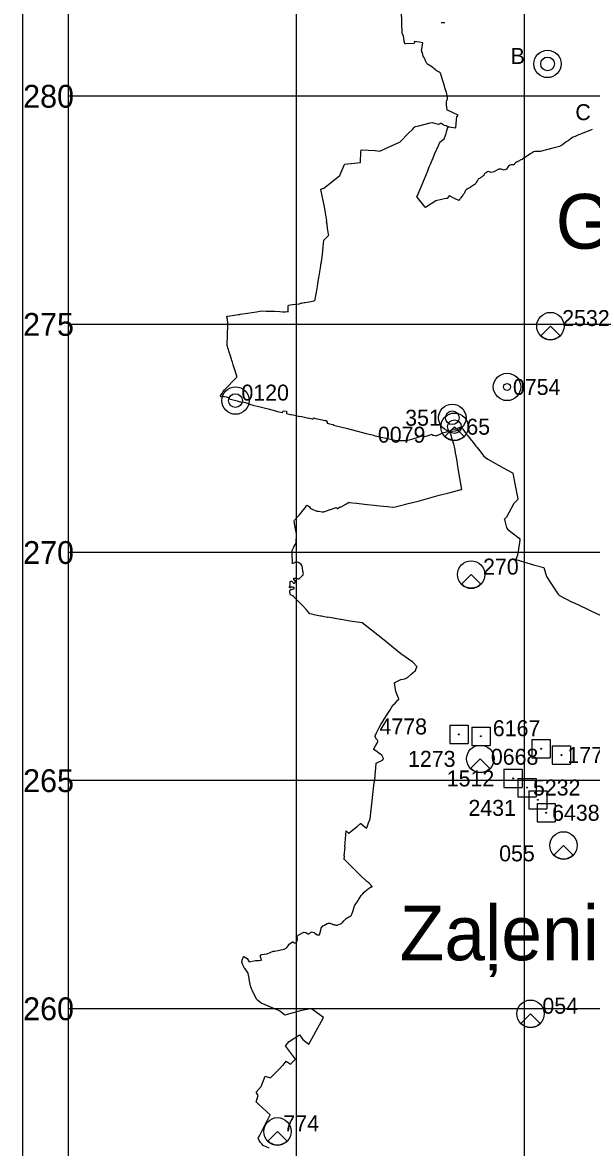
# Model space of a CAD drawing. Extents: x 459000 to 506121, y 222400 to 317452.
# Drawn here: x 459000 to 471473, y 256960 to 281617 of the extents above; entities that cross this region are included whole.
import ezdxf

# ---------------------------------------------------------------- set-up
doc = ezdxf.new("R2010")
doc.units = 0
for name, color, linetype in [('grunts_reperi', 7, 'Continuous'), ('novada_robeza', 7, 'Continuous'), ('pagastu_nosaukumi', 7, 'Continuous'), ('pagastu_robezas', 7, 'Continuous'), ('Ramis', 7, 'Continuous'), ('savietotie_ar_poligonometrijas_punktiem', 7, 'Continuous'), ('sienas_markas', 7, 'Continuous'), ('sienas_reperi', 7, 'Continuous')]:
    doc.layers.add(name, color=color, linetype=linetype)

msp = doc.modelspace()

# ---------------------------------------------------------------- linework, layer by layer
at = {"layer": 'grunts_reperi'}
for radius in [300, 75]:
    msp.add_circle((469621, 273629), radius, dxfattribs=at)
at = {"layer": 'novada_robeza'}
for points in [[(468327, 279317), (468330, 279314), (468334, 279322), (468335, 279328), (468336, 279334), (468343, 279334), (468346, 279333), (468496, 279311), (468516, 279490), (468522, 279550), (468549, 279589), (468316, 279694), (468309, 279697), (468306, 279721), (468303, 279739), (468300, 279765), (468297, 279789), (468296, 279798), (468292, 279822), (468291, 279847), (468293, 279865), (468295, 279879), (468304, 279909), (468315, 279947), (468318, 279961), (468319, 279968), (468318, 279983), (468316, 279998), (468310, 280019), (468291, 280079), (468266, 280164), (468233, 280274), (468214, 280341), (468186, 280433), (468183, 280443), (468170, 280486), (468166, 280497), (468161, 280506), (468156, 280512), (468148, 280520), (468144, 280522), (468139, 280526), (468111, 280540), (468087, 280552), (468071, 280562), (468057, 280573), (468043, 280584), (467948, 280656), (467881, 280704), (467880, 280705), (467864, 280721), (467849, 280744), (467834, 280774), (467810, 280832), (467802, 280845), (467799, 280849), (467796, 280854), (467794, 280858), (467782, 280878), (467766, 280951), (467754, 280975), (467749, 281009), (467748, 281012), (467752, 281034), (467775, 281173), (467698, 281184), (467596, 281202), (467590, 281200), (467589, 281193), (467591, 281174), (467588, 281155), (467395, 281146), (467387, 281146), (467383, 281148), (467381, 281149), (467368, 281199), (467368, 281214), (467349, 281325), (467326, 281375), (467314, 281614), (467307, 281871)], [(468178, 281619), (468196, 281616), (468211, 281616), (468217, 281615), (468222, 281614), (468237, 281615), (468242, 281614), (468243, 281614), (468251, 281616), (468259, 281617)], [(463333, 273425), (463338, 273433), (463367, 273477), (463399, 273528), (463425, 273566), (463687, 273827), (463697, 273847), (463698, 273866), (463641, 274046), (463619, 274114), (463617, 274117), (463600, 274170), (463588, 274208), (463579, 274235), (463550, 274330), (463532, 274393), (463486, 274538), (463483, 274549), (463487, 274624), (463493, 274695), (463497, 274805), (463497, 274805), (463502, 274947), (463501, 274947), (463501, 274952), (463500, 274981), (463500, 274994), (463501, 275007), (463501, 275027), (463501, 275038), (463500, 275055), (463498, 275067), (463496, 275080), (463494, 275093), (463492, 275102), (463491, 275112), (463490, 275120), (463488, 275133), (463484, 275153), (463482, 275160), (463481, 275166), (463480, 275174), (463501, 275178), (463734, 275216), (463755, 275219), (463774, 275222), (463930, 275247), (464028, 275262), (464128, 275278), (464240, 275296), (464342, 275293), (464472, 275287), (464481, 275287), (464525, 275287), (464642, 275281), (464698, 275278), (464725, 275277), (464756, 275277), (464799, 275280), (464828, 275282), (464827, 275286), (464825, 275389), (464829, 275421), (464918, 275434), (464987, 275443), (465069, 275453), (465072, 275450), (465075, 275454), (465087, 275460), (465095, 275463), (465115, 275467), (465172, 275477), (465198, 275480), (465331, 275503), (465387, 275518), (465402, 275526), (465412, 275536), (465418, 275553), (465458, 275789), (465465, 275834), (465476, 275897), (465497, 276024), (465503, 276062), (465533, 276241), (465549, 276349), (465553, 276374), (465573, 276534), (465594, 276702), (465606, 276848), (465610, 276853), (465718, 276959), (465708, 276973), (465707, 276978), (465692, 277068), (465688, 277104), (465675, 277194), (465667, 277251), (465669, 277271), (465618, 277579), (465539, 277954), (465537, 277962), (465541, 277963), (465595, 277986), (465599, 277981), (465746, 278096), (465883, 278203), (465959, 278260), (465989, 278337), (466058, 278501), (466063, 278512), (466064, 278512), (466412, 278549), (466407, 278562), (466420, 278765), (466425, 278827), (466732, 278809), (466783, 278804), (466833, 278799), (466946, 278851), (467035, 278893), (467183, 278956), (467235, 278977), (467247, 278983), (467273, 278996), (467289, 279011), (467457, 279184), (467465, 279194), (467546, 279275), (467589, 279318), (467602, 279329), (467611, 279334), (467618, 279335), (467689, 279354), (467940, 279419), (467977, 279426), (468084, 279398), (468119, 279389), (468127, 279389), (468154, 279405), (468161, 279407), (468165, 279409), (468173, 279409), (468182, 279409), (468184, 279408), (468187, 279406), (468200, 279396), (468218, 279381), (468230, 279371), (468243, 279368), (468280, 279361), (468286, 279358), (468327, 279317)], [(463333, 273425), (463340, 273423), (463396, 273409), (463400, 273429), (463431, 273419), (463462, 273409), (463534, 273390), (463527, 273371), (463674, 273335), (463704, 273322), (463731, 273315), (463804, 273295), (463820, 273305), (463964, 273269), (463961, 273259), (463979, 273261), (463976, 273250), (464046, 273233), (464077, 273225), (464208, 273191), (464386, 273147), (464545, 273106), (464593, 273094), (464703, 273069), (464712, 273108), (464788, 273098), (464787, 273049), (464901, 273020), (464904, 273019), (464906, 273028), (465079, 272984), (465081, 272990), (465123, 272979), (465266, 272944), (465268, 272952), (465374, 272926), (465380, 272950), (465425, 272937), (465531, 272917), (465638, 272896), (465647, 272894), (465656, 272892), (465679, 272860), (465677, 272834), (465687, 272832), (465705, 272829), (465763, 272815), (465822, 272801), (465821, 272796), (465820, 272791), (465971, 272753), (466122, 272715), (466530, 272612), (466702, 272569), (466703, 272568), (466704, 272568), (466857, 272532), (467011, 272496), (467132, 272469), (467135, 272468), (467207, 272459), (467303, 272455), (467312, 272456), (467349, 272452), (467413, 272457), (467487, 272470), (467556, 272490), (467787, 272565), (467792, 272549), (467797, 272533), (467890, 272562), (467982, 272591), (467986, 272581), (467989, 272571), (468016, 272569), (468044, 272567), (468065, 272559), (468225, 272627), (468344, 272657), (468345, 272657), (468358, 272662), (468371, 272667)], [(463847, 261148), (463849, 261147), (463851, 261146), (463890, 261123), (463928, 261099), (463948, 261063), (463968, 261026), (464109, 261056), (464136, 261058), (464141, 261058), (464188, 261061), (464236, 261063), (464214, 261141), (464211, 261150), (464240, 261191), (464294, 261198), (464352, 261205), (464360, 261206), (464494, 261266), (464522, 261266), (464603, 261280), (464660, 261291), (464707, 261301), (464735, 261308), (464780, 261328), (464798, 261344), (464821, 261378), (464848, 261419), (464920, 261469), (464928, 261468), (464964, 261448), (464980, 261445), (464994, 261447), (465004, 261456), (465010, 261463), (465019, 261490), (465028, 261524), (465023, 261574), (465029, 261599), (465041, 261614), (465152, 261673), (465167, 261683), (465211, 261675), (465244, 261648), (465255, 261643), (465272, 261640), (465287, 261646), (465310, 261670), (465331, 261682), (465348, 261685), (465367, 261682), (465394, 261671), (465431, 261645), (465459, 261623), (465481, 261620), (465502, 261623), (465508, 261623), (465538, 261727), (465549, 261765), (465562, 261787), (465572, 261799), (465587, 261815), (465606, 261826), (465678, 261866), (465695, 261873), (465710, 261875), (465714, 261876), (465717, 261877), (465724, 261876), (465731, 261876), (465736, 261875), (465742, 261874), (465752, 261870), (465762, 261867), (465787, 261859), (465812, 261851), (465829, 261845), (465846, 261840), (465855, 261837), (465865, 261835), (465871, 261834), (465878, 261833), (465884, 261833), (465890, 261833), (465900, 261836), (465910, 261840), (465934, 261846), (465958, 261852), (465972, 261859), (465985, 261867), (465998, 261880), (466012, 261892), (466041, 261925), (466071, 261959), (466082, 261967), (466094, 261976), (466128, 261998), (466162, 262019), (466170, 262021), (466178, 262024), (466186, 262030), (466202, 262043), (466218, 262074), (466238, 262133), (466246, 262156), (466280, 262255), (466355, 262374), (466375, 262400), (466387, 262426), (466425, 262485), (466457, 262522), (466492, 262554), (466496, 262561), (466533, 262595), (466582, 262637), (466606, 262654), (466641, 262674), (466649, 262676), (466668, 262676), (466662, 262682), (466595, 262764), (466546, 262791), (466401, 262928), (466393, 262936), (466152, 263177), (466150, 263179), (466147, 263182), (466056, 263270), (466052, 263270), (466055, 263350), (466054, 263355), (466070, 263546), (466069, 263549), (466069, 263553), (466095, 263900), (466097, 263902), (466143, 263848), (466147, 263846), (466157, 263850), (466206, 263891), (466333, 263996), (466408, 264059), (466413, 264062), (466477, 264012), (466544, 263959), (466547, 263965), (466587, 264076), (466619, 264162), (466634, 264292), (466712, 264960), (466707, 264962), (466722, 265009), (466731, 265124), (466742, 265281), (466750, 265384), (466892, 265446), (466911, 265480), (466915, 265486), (466875, 265560), (466821, 265599), (466764, 265636), (466706, 265674), (466704, 265677), (466701, 265684), (466700, 265693), (466704, 265701), (466737, 265765), (466772, 265825), (466786, 265855), (466786, 265867), (466780, 265885), (466774, 265895), (466763, 265913), (466726, 265975), (466734, 265991), (466742, 266009), (466761, 266047), (466824, 266178), (466856, 266231), (466910, 266317), (466917, 266327), (467009, 266475), (467051, 266540), (467121, 266652), (467166, 266697), (467222, 266754), (467233, 266764), (467251, 266789), (467246, 266792), (467242, 266805), (467184, 266955), (467151, 267142), (467180, 267162), (467290, 267220), (467380, 267234), (467437, 267260), (467514, 267326), (467612, 267411), (467647, 267492), (467651, 267496), (467553, 267600), (467294, 267781), (467293, 267782), (466930, 268076), (466654, 268297), (466447, 268458), (466444, 268458), (466175, 268499), (465984, 268532), (465979, 268531), (465966, 268534), (465960, 268535), (465814, 268559), (465808, 268560), (465694, 268582), (465678, 268578), (465557, 268604), (465535, 268608), (465424, 268629), (465394, 268635), (465334, 268648), (465301, 268653), (465223, 268743), (465145, 268833), (465143, 268834), (465141, 268836), (465092, 268885), (465042, 268934), (465039, 268937), (465036, 268940), (465022, 268955), (465008, 268969), (464997, 268980), (464985, 268992), (464974, 269003), (464963, 269015), (464952, 269025), (464941, 269035), (464937, 269041), (464933, 269046), (464931, 269048), (464928, 269049), (464927, 269049), (464898, 269063), (464868, 269076), (464859, 269078), (464861, 269082), (464864, 269086), (464867, 269092), (464869, 269096), (464870, 269102), (464870, 269109), (464869, 269117), (464867, 269122), (464863, 269127), (464861, 269132), (464858, 269142), (464857, 269149), (464858, 269156), (464857, 269159), (464858, 269162), (464862, 269167), (464865, 269167), (464866, 269170), (464869, 269172), (464872, 269176), (464873, 269177), (464876, 269180), (464877, 269182), (464877, 269184), (464878, 269184), (464883, 269187), (464884, 269190), (464886, 269190), (464887, 269191), (464898, 269192), (464912, 269195), (464922, 269197), (464945, 269201), (464950, 269202), (464954, 269206), (464957, 269211), (464958, 269218), (464957, 269223), (464954, 269228), (464948, 269233), (464941, 269237), (464936, 269240), (464926, 269243), (464910, 269244), (464896, 269244), (464889, 269241), (464884, 269238), (464878, 269233), (464875, 269227), (464869, 269225), (464866, 269224), (464857, 269224), (464854, 269227), (464852, 269228), (464851, 269229), (464850, 269233), (464850, 269236), (464849, 269239), (464849, 269242), (464850, 269245), (464851, 269253), (464853, 269254), (464854, 269256), (464856, 269258), (464859, 269263), (464860, 269265), (464864, 269268), (464866, 269270), (464867, 269273), (464868, 269276), (464869, 269280), (464869, 269283), (464869, 269288), (464869, 269294), (464867, 269305), (464868, 269310), (464869, 269315), (464869, 269321), (464869, 269326), (464870, 269332), (464871, 269345), (464871, 269351), (464871, 269356), (464869, 269358), (464870, 269360), (464869, 269360), (464871, 269362), (464872, 269365), (464874, 269368), (464876, 269372), (464878, 269372), (464888, 269375), (464899, 269372), (464914, 269364), (464925, 269352), (464933, 269339), (464936, 269332), (464943, 269327), (464948, 269326), (464959, 269328), (464964, 269332), (464970, 269337), (464975, 269349), (464980, 269362), (464981, 269367), (464982, 269372), (464982, 269375), (464981, 269378), (464979, 269380), (464977, 269382), (464969, 269387), (464960, 269392), (464954, 269397), (464951, 269402), (464948, 269407), (464947, 269413), (464946, 269420), (464947, 269425), (464947, 269430), (464949, 269433), (464951, 269436), (464955, 269437), (464960, 269438), (464968, 269438), (464975, 269439), (464985, 269439), (464995, 269440), (464998, 269439), (465002, 269439), (465014, 269434), (465026, 269428), (465033, 269426), (465040, 269423), (465046, 269423), (465052, 269422), (465055, 269423), (465059, 269424), (465062, 269426), (465065, 269428), (465071, 269433), (465077, 269437), (465086, 269447), (465096, 269457), (465101, 269462), (465106, 269466), (465114, 269476), (465122, 269486), (465146, 269506), (465159, 269542), (465145, 269587), (465141, 269671), (465133, 269704), (465112, 269736), (465080, 269762), (465051, 269782), (465024, 269788), (464986, 269787), (464935, 269757), (464922, 269756), (464916, 269764), (464912, 269767), (464916, 269795), (464917, 269808), (464917, 269818), (464917, 269834), (464917, 269846), (464916, 269864), (464915, 269877), (464914, 269885), (464914, 269892), (464914, 269896), (464908, 269993), (464908, 270030), (464908, 270046), (464937, 270101), (464957, 270136), (464997, 270204), (464999, 270218), (465001, 270275), (464999, 270289), (465005, 270328), (465003, 270408), (464975, 270556), (464952, 270679), (464951, 270690), (464952, 270694), (464961, 270707), (465069, 270828), (465154, 270927), (465197, 270979), (465231, 271035), (465260, 271022), (465288, 271000), (465310, 270966), (465452, 270910), (465474, 270907), (465488, 270905), (465566, 270892), (465604, 270894), (465628, 270899), (465689, 270920), (465743, 270940), (465753, 270944), (465879, 270988), (465885, 270982), (465900, 270962), (465906, 270966), (465964, 271001), (465969, 270994), (466090, 271058), (466157, 271101), (466157, 271099), (466319, 271081), (466555, 271055), (466710, 271038), (466827, 271025), (466917, 271015), (467001, 271006), (467112, 270993), (467117, 270993), (467168, 271005), (467405, 271063), (467451, 271073), (467671, 271128), (468135, 271257), (468136, 271258), (468372, 271317), (468615, 271380), (468627, 271382), (468585, 271632), (468544, 271882), (468525, 271999), (468506, 272116), (468494, 272185), (468483, 272254), (468470, 272313), (468457, 272372), (468435, 272440), (468414, 272509), (468413, 272513), (468388, 272593), (468385, 272601), (468378, 272634), (468371, 272667)], [(464119, 257963), (464165, 258102), (464123, 258170), (464234, 258296), (464319, 258521), (464436, 258489), (464571, 258619), (464625, 258678), (464640, 258694), (464698, 258758), (464717, 258763), (464782, 258852), (464876, 258784), (464988, 258894), (464764, 259190), (464848, 259282), (465069, 259427), (465146, 259325), (465278, 259222), (465352, 259359), (465432, 259500), (465553, 259730), (465595, 259808), (465335, 260001), (465317, 260000), (465115, 259963), (464751, 259859), (464637, 259952), (464230, 260122), (464155, 260192), (464130, 260213), (464032, 260409), (464021, 260437), (464012, 260463), (464001, 260505), (463972, 260650), (463967, 260670), (463960, 260711), (463946, 260772), (463936, 260795), (463933, 260801), (463929, 260806), (463929, 260806), (463929, 260805), (463900, 260845), (463871, 260884), (463861, 260901), (463851, 260917), (463844, 260931), (463837, 260945), (463830, 260961), (463824, 260978), (463817, 261001), (463811, 261025), (463811, 261033), (463812, 261042), (463813, 261057), (463815, 261071), (463819, 261080), (463822, 261089), (463835, 261118), (463847, 261148)], [(464407, 256948), (464341, 256976), (464275, 257004), (464247, 257037), (464219, 257070), (464191, 257115), (464163, 257161), (464174, 257179), (464194, 257218), (464297, 257418), (464360, 257544), (464428, 257675), (464338, 257757), (464184, 257904), (464125, 257958), (464119, 257963)]]:
    msp.add_lwpolyline(points, dxfattribs=at)
at = {"layer": 'pagastu_robezas'}
for points in [[(471484, 279275), (471397, 279235), (471280, 279192), (471215, 279163), (471190, 279155), (471174, 279144), (471115, 279118), (471071, 279104), (471015, 279070), (471005, 279060), (470997, 279051), (470958, 279026), (470917, 279000), (470879, 278972), (470840, 278936), (470813, 278920), (470774, 278902), (470739, 278888), (470711, 278885), (470627, 278862), (470349, 278790), (470293, 278789), (470239, 278792), (470204, 278779), (470173, 278763), (470145, 278743), (470133, 278735), (469967, 278626), (469951, 278613), (469926, 278609), (469906, 278598), (469893, 278587), (469870, 278576), (469847, 278563), (469828, 278554), (469809, 278540), (469786, 278517), (469775, 278502), (469761, 278495), (469731, 278496), (469711, 278498), (469690, 278493), (469656, 278469), (469643, 278461), (469607, 278405), (469561, 278377), (469494, 278404), (469443, 278400), (469330, 278341), (469274, 278328), (469216, 278352), (469190, 278347), (469130, 278300), (469122, 278285), (469102, 278266), (469095, 278253), (469080, 278239), (469079, 278238), (469065, 278227), (469048, 278217), (469034, 278208), (469015, 278198), (468997, 278189), (468987, 278176), (468977, 278159), (468964, 278142), (468958, 278132), (468942, 278110), (468935, 278092), (468926, 278079), (468916, 278068), (468897, 278060), (468884, 278050), (468865, 278037), (468850, 278026), (468836, 278013), (468816, 278002), (468803, 277994), (468785, 277983), (468771, 277976), (468748, 277963), (468739, 277961), (468730, 277956), (468727, 277953), (468722, 277949), (468710, 277936), (468703, 277925), (468701, 277922), (468695, 277907), (468687, 277885), (468679, 277870), (468661, 277844), (468654, 277832), (468636, 277812), (468624, 277796), (468609, 277774), (468599, 277760), (468586, 277744), (468573, 277727), (468572, 277725), (468565, 277716), (468563, 277715), (468553, 277720), (468469, 277762), (468360, 277818), (468356, 277821), (468310, 277760), (468294, 277759), (468254, 277752), (468186, 277740), (468187, 277734), (468057, 277706), (467832, 277561), (467824, 277571), (467648, 277790), (467646, 277794), (467646, 277799), (467722, 277979), (467776, 278104), (467810, 278187), (467883, 278366), (467884, 278370), (467925, 278465), (467944, 278512), (468000, 278647), (468042, 278743), (468116, 278918), (468125, 278939), (468149, 278997), (468245, 279068), (468285, 279186), (468305, 279246), (468327, 279317)], [(468371, 272667), (468389, 272679), (468407, 272691), (468436, 272701), (468464, 272711), (468471, 272702), (468478, 272693), (468488, 272701), (468499, 272710), (468559, 272732), (468619, 272753), (468627, 272743), (468634, 272733), (468644, 272718), (468654, 272702), (468706, 272633), (468759, 272564), (468765, 272557), (468801, 272511), (468838, 272464), (468848, 272452), (468857, 272440), (468939, 272334), (468958, 272310), (469024, 272226), (469108, 272118), (469189, 272054), (469192, 272052), (469197, 272047), (469554, 271850), (469742, 271744), (469748, 271741), (469789, 271504), (469794, 271505), (469855, 271179), (469864, 271166), (469837, 271139), (469770, 271072), (469607, 270778), (469561, 270726), (469564, 270723), (469613, 270545), (469618, 270537), (469630, 270513), (469735, 270431), (469886, 270314), (469899, 270294), (469904, 270272), (469897, 270222), (469854, 269942), (469815, 269847), (470204, 269731), (470427, 269674), (470486, 269475), (470722, 269115), (470740, 269088), (470775, 269057), (471036, 268923), (471079, 268903), (471369, 268766), (471456, 268723), (471946, 268493)]]:
    msp.add_lwpolyline(points, dxfattribs=at)
at = {"layer": 'Ramis'}
for p, q in [((459000, 311000), (459000, 222400)), ((460000, 310000), (460000, 240000)), ((465000, 310000), (465000, 240000)), ((470000, 310000), (470000, 240000)), ((505000, 280000), (460000, 280000)), ((505000, 275000), (460000, 275000)), ((505000, 270000), (460000, 270000)), ((505000, 265000), (460000, 265000)), ((505000, 260000), (460000, 260000))]:
    msp.add_line(p, q, dxfattribs=at)
at = {"layer": 'savietotie_ar_poligonometrijas_punktiem'}
for p, q in [((468366, 266213), (468766, 266213)), ((468366, 266213), (468366, 265813)), ((468766, 266213), (468766, 265813)), ((468850, 266174), (469250, 266174)), ((468850, 266174), (468850, 265774)), ((469250, 266174), (469250, 265774)), ((468366, 265813), (468766, 265813)), ((470167, 265899), (470567, 265899)), ((470167, 265899), (470167, 265499)), ((470567, 265899), (470567, 265499)), ((468850, 265774), (469250, 265774)), ((470613, 265761), (471013, 265761)), ((470613, 265761), (470613, 265361)), ((471013, 265761), (471013, 265361)), ((470167, 265499), (470567, 265499)), ((470613, 265361), (471013, 265361)), ((469553, 265249), (469953, 265249)), ((469553, 265249), (469553, 264849)), ((469953, 265249), (469953, 264849)), ((469553, 264849), (469953, 264849)), ((469859, 265049), (470259, 265049)), ((469859, 265049), (469859, 264649)), ((470259, 265049), (470259, 264649)), ((469859, 264649), (470259, 264649)), ((470096, 264779), (470496, 264779)), ((470096, 264779), (470096, 264379)), ((470496, 264779), (470496, 264379)), ((470096, 264379), (470496, 264379)), ((470279, 264496), (470679, 264496)), ((470279, 264496), (470279, 264096)), ((470679, 264496), (470679, 264096)), ((470279, 264096), (470679, 264096))]:
    msp.add_line(p, q, dxfattribs=at)
for centre in [(468566, 266013), (469050, 265974), (470367, 265699), (470813, 265561), (469753, 265049), (470059, 264849), (470296, 264579), (470479, 264296)]:
    msp.add_circle(centre, 10, dxfattribs=at)
at = {"layer": 'sienas_markas'}
for centre, radius in [((470509, 280708), 300), ((470509, 280708), 150), ((463669, 273330), 300), ((463669, 273330), 150), ((468422, 272954), 300), ((468469, 272758), 300), ((468422, 272954), 150), ((468469, 272758), 150)]:
    msp.add_circle(centre, radius, dxfattribs=at)
at = {"layer": 'sienas_reperi'}
for p, q in [((470571, 274964), (470359, 274752)), ((470784, 274752), (470571, 274964)), ((468469, 272758), (468257, 272546)), ((468681, 272546), (468469, 272758)), ((468836, 269517), (468624, 269305)), ((469048, 269305), (468836, 269517)), ((469036, 265478), (468824, 265266)), ((469248, 265266), (469036, 265478)), ((470861, 263582), (470649, 263370)), ((471074, 263370), (470861, 263582)), ((470137, 259892), (469925, 259680)), ((470349, 259680), (470137, 259892)), ((464588, 257314), (464375, 257102)), ((464800, 257102), (464588, 257314))]:
    msp.add_line(p, q, dxfattribs=at)
for centre in [(470571, 274964), (468469, 272758), (468836, 269517), (469036, 265478), (470861, 263582), (470137, 259892), (464588, 257314)]:
    msp.add_circle(centre, 300, dxfattribs=at)
for centre in [(470571, 274964), (468469, 272758), (468836, 269517), (469036, 265478), (470861, 263582), (470137, 259892), (464588, 257314)]:
    msp.add_arc(centre, 300, 225, 315, dxfattribs=at)

# ---------------------------------------------------------------- texts
at = {"layer": 'grunts_reperi'}
msp.add_text(' 0754', height=350, dxfattribs=at).set_placement((469621, 273454))
at = {"layer": 'pagastu_nosaukumi'}
for s, p in [('Glūdas', (470689, 276659)), ('Zaļenieku', (467267, 261063))]:
    msp.add_text(s, height=1200, dxfattribs=at).set_placement(p)
at = {"layer": 'Ramis'}
for s, p in [('280', (459014, 279750)), ('275', (459013, 274750)), ('270', (459014, 269750)), ('265', (459013, 264750)), ('260', (459014, 259750))]:
    msp.add_text(s, height=500, dxfattribs=at).set_placement(p)
at = {"layer": 'savietotie_ar_poligonometrijas_punktiem'}
for s, p in [('4778  ', (466826, 266013)), ('  6167', (469050, 265974)), ('0668', (469267, 265349)), (' 1779', (470813, 265386)), ('1512  ', (468300, 264874)), (' 5232', (470059, 264674)), ('2431   ', (468776, 264229)), (' 6438', (470479, 264121))]:
    msp.add_text(s, height=350, dxfattribs=at).set_placement(p)
at = {"layer": 'sienas_markas'}
for s, p in [('B  ', (469701, 280708)), ('C  ', (471119, 279476)), (' 0120', (463669, 273330)), ('351  ', (467389, 272779)), ('0079  ', (466791, 272408))]:
    msp.add_text(s, height=350, dxfattribs=at).set_placement(p)
at = {"layer": 'sienas_reperi'}
for s, p in [('  2532', (470571, 274964)), ('  65', (468469, 272583)), ('  270', (468836, 269517)), ('1273  ', (467451, 265303)), ('055  ', (469449, 263232)), ('  054', (470137, 259892)), (' 774', (464588, 257314))]:
    msp.add_text(s, height=350, dxfattribs=at).set_placement(p)

doc.saveas('drawing.dxf')
